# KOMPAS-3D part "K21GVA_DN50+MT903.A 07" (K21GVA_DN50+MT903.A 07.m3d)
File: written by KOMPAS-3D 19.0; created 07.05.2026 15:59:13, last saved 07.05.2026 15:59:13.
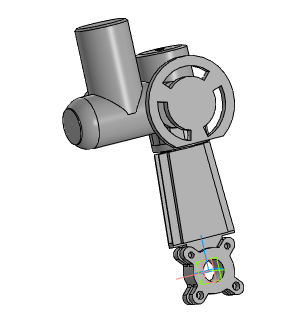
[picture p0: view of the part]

Document properties: Автор: Энергия; Полное имя файла: ..\K21GVA_DN50-DN1000+MT903.A\K21GVA_DN50+MT903.A 07.a3d

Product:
- Part/product: K21GVA_DN50+MT903.A 07
    Масса: 72.2791

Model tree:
1. Операция без истории:1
